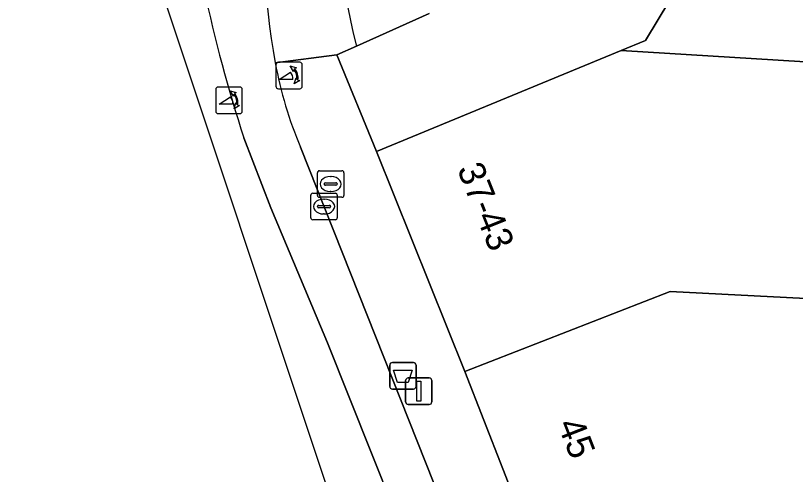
# Model space of a CAD drawing. Extents: x 160856 to 161310, y 384024 to 384878.
# Drawn here: x 160864.45 to 160893.85, y 384793.33 to 384810.61 of the extents above; entities that cross this region are included whole.
import ezdxf

# ---------------------------------------------------------------- set-up
doc = ezdxf.new("R2010")
doc.units = 0
for name, color, linetype in [('IMGEO_Afvalbak', 7, 'Continuous'), ('IMGEO_Brandkraan', 7, 'Continuous'), ('IMGEO_Erf', 7, 'Continuous'), ('IMGEO_Kolk', 7, 'Continuous'), ('IMGEO_Lichtmast', 7, 'Continuous'), ('IMGEO_Pand', 7, 'Continuous'), ('IMGEO_Pand_nummerreeks', 7, 'Continuous'), ('IMGEO_Pand_overbouw', 7, 'Continuous'), ('IMGEO_Poller', 7, 'Continuous'), ('IMGEO_Rijbaan_lokaal_gesloten', 7, 'Continuous'), ('IMGEO_Voetpad_open', 7, 'Continuous')]:
    doc.layers.add(name, color=color, linetype=linetype)

msp = doc.modelspace()

# ---------------------------------------------------------------- linework, layer by layer
at = {"layer": 'IMGEO_Afvalbak'}
for p, q in [((160878.555, 384796.644), (160878.555, 384797.444)), ((160878.555, 384797.444), (160878.555, 384796.644)), ((160878.655, 384797.544), (160879.445, 384797.544)), ((160879.445, 384797.544), (160878.655, 384797.544)), ((160879.545, 384797.444), (160879.545, 384796.644)), ((160879.545, 384796.644), (160879.545, 384797.444)), ((160879.445, 384796.544), (160878.655, 384796.544)), ((160878.655, 384796.544), (160879.445, 384796.544))]:
    msp.add_line(p, q, dxfattribs=at)
msp.add_lwpolyline([(160878.698, 384797.258), (160879.402, 384797.258), (160879.253, 384796.788), (160878.847, 384796.788), (160878.698, 384797.258)], dxfattribs=at)
for centre, start, end in [((160878.655, 384797.444), 90, 180), ((160878.655, 384797.444), 90, 180), ((160879.445, 384797.444), 0, 90), ((160879.445, 384797.444), 360, 90), ((160878.655, 384796.644), 180, 270), ((160878.655, 384796.644), 180, 270), ((160879.445, 384796.644), 270, 0), ((160879.445, 384796.644), 270, 0)]:
    msp.add_arc(centre, 0.1, start, end, dxfattribs=at)
at = {"layer": 'IMGEO_Brandkraan'}
for p, q in [((160875.827, 384803.842), (160875.827, 384804.694)), ((160875.902, 384804.768), (160876.754, 384804.768)), ((160876.828, 384804.694), (160876.828, 384803.842)), ((160876.315, 384804.548), (160876.34, 384804.548)), ((160876.086, 384804.262), (160876.086, 384804.274)), ((160876.524, 384804.225), (160876.126, 384804.225)), ((160876.129, 384804.311), (160876.527, 384804.311)), ((160876.57, 384804.274), (160876.57, 384804.262)), ((160876.338, 384803.988), (160876.313, 384803.988)), ((160876.754, 384803.768), (160875.902, 384803.768))]:
    msp.add_line(p, q, dxfattribs=at)
for points in [[(160875.827, 384803.842), (160875.827, 384804.694)], [(160875.902, 384804.768), (160876.754, 384804.768)], [(160876.828, 384804.694), (160876.828, 384803.842)], [(160876.754, 384803.768), (160875.902, 384803.768)]]:
    msp.add_lwpolyline(points, dxfattribs=at)
for centre, radius, start, end in [((160875.904, 384804.692), 0.0765, 91.552, 178.448), ((160875.904, 384804.692), 0.0765, 91.552, 178.448), ((160876.752, 384804.692), 0.0765, 1.552, 88.448), ((160876.752, 384804.692), 0.0765, 1.552, 88.448), ((160876.126, 384804.271), 0.0403, 85.8775, 175.7526), ((160876.123, 384804.261), 0.0366, 178.938, 274.7102), ((160876.527, 384804.268), 0.043, 264.8664, 352.4533), ((160876.531, 384804.273), 0.0386, 1.7309, 96.639), ((160875.904, 384803.844), 0.0765, 181.552, 268.448), ((160875.904, 384803.844), 0.0765, 181.552, 268.448), ((160876.752, 384803.844), 0.0765, 271.552, 358.448), ((160876.752, 384803.844), 0.0765, 271.552, 358.448)]:
    msp.add_arc(centre, radius, start, end, dxfattribs=at)
for centre, major_axis, ratio, start_param, end_param in [((160876.314, 384804.268), (-0.387, 0.002), 0.722429, 4.712389, 7.853982), ((160876.339, 384804.268), (-0.39, 0.002), 0.717154, 1.570796, 4.712389)]:
    msp.add_ellipse(centre, major_axis=major_axis, ratio=ratio, start_param=start_param, end_param=end_param, dxfattribs=at)
at = {"layer": 'IMGEO_Erf'}
msp.add_lwpolyline([(160961.197, 384839.783), (160936.502, 384833.624), (160932.413, 384832.61), (160896.629, 384823.652), (160888.199, 384809.678), (160887.275, 384809.297), (160905.032, 384808.21), (160908.857, 384799.197), (160924.302, 384798.324), (160924.223, 384796.935), (160953.576, 384795.276), (160956.275, 384793.744), (160958.566, 384819.819)], dxfattribs=at)
at = {"layer": 'IMGEO_Kolk'}
for p, q in [((160875.576, 384802.994), (160875.576, 384803.846)), ((160875.651, 384803.92), (160876.503, 384803.92)), ((160876.577, 384803.846), (160876.577, 384802.994)), ((160876.064, 384803.7), (160876.089, 384803.7)), ((160875.835, 384803.414), (160875.835, 384803.426)), ((160876.273, 384803.377), (160875.875, 384803.377)), ((160875.878, 384803.463), (160876.276, 384803.463)), ((160876.319, 384803.426), (160876.319, 384803.414)), ((160876.503, 384802.92), (160875.651, 384802.92)), ((160876.087, 384803.14), (160876.062, 384803.14))]:
    msp.add_line(p, q, dxfattribs=at)
for points in [[(160875.576, 384802.994), (160875.576, 384803.846)], [(160875.651, 384803.92), (160876.503, 384803.92)], [(160876.577, 384803.846), (160876.577, 384802.994)], [(160876.503, 384802.92), (160875.651, 384802.92)]]:
    msp.add_lwpolyline(points, dxfattribs=at)
for centre, radius, start, end in [((160875.653, 384803.844), 0.0765, 91.552, 178.448), ((160875.653, 384803.844), 0.0765, 91.552, 178.448), ((160876.501, 384803.844), 0.0765, 1.552, 88.448), ((160876.501, 384803.844), 0.0765, 1.552, 88.448), ((160875.875, 384803.423), 0.0403, 85.8775, 175.7526), ((160875.872, 384803.413), 0.0366, 178.938, 274.7102), ((160876.276, 384803.42), 0.043, 264.8664, 352.4533), ((160876.28, 384803.425), 0.0386, 1.7309, 96.639), ((160875.653, 384802.996), 0.0765, 181.552, 268.448), ((160875.653, 384802.996), 0.0765, 181.552, 268.448), ((160876.501, 384802.996), 0.0765, 271.552, 358.448), ((160876.501, 384802.996), 0.0765, 271.552, 358.448)]:
    msp.add_arc(centre, radius, start, end, dxfattribs=at)
for centre, major_axis, ratio, start_param, end_param in [((160876.063, 384803.42), (-0.387, 0.002), 0.722429, 4.712389, 7.853982), ((160876.088, 384803.42), (-0.39, 0.002), 0.717154, 1.570796, 4.712389)]:
    msp.add_ellipse(centre, major_axis=major_axis, ratio=ratio, start_param=start_param, end_param=end_param, dxfattribs=at)
at = {"layer": 'IMGEO_Lichtmast'}
for p, q in [((160879.151, 384796.062), (160879.151, 384796.862)), ((160879.151, 384796.862), (160879.151, 384796.062)), ((160879.251, 384796.962), (160880.041, 384796.962)), ((160880.041, 384796.962), (160879.251, 384796.962)), ((160880.141, 384796.862), (160880.141, 384796.062)), ((160880.141, 384796.062), (160880.141, 384796.862)), ((160880.041, 384795.962), (160879.251, 384795.962)), ((160879.251, 384795.962), (160880.041, 384795.962))]:
    msp.add_line(p, q, dxfattribs=at)
msp.add_lwpolyline([(160879.571, 384796.837), (160879.721, 384796.837), (160879.721, 384796.087), (160879.571, 384796.087), (160879.571, 384796.837)], dxfattribs=at)
for centre, start, end in [((160879.251, 384796.862), 90, 180), ((160879.251, 384796.862), 90, 180), ((160880.041, 384796.862), 0, 90), ((160880.041, 384796.862), 360, 90), ((160879.251, 384796.062), 180, 270), ((160879.251, 384796.062), 180, 270), ((160880.041, 384796.062), 270, 0), ((160880.041, 384796.062), 270, 0)]:
    msp.add_arc(centre, 0.1, start, end, dxfattribs=at)
at = {"layer": 'IMGEO_Pand'}
msp.add_lwpolyline([(160880.046, 384810.689), (160877.299, 384809.467), (160876.56, 384809.138), (160878.06, 384805.492), (160887.275, 384809.297), (160888.199, 384809.678), (160896.629, 384823.652), (160932.413, 384832.61)], dxfattribs=at)
for points in [[(160878.06, 384805.492), (160881.386, 384797.201), (160889.13, 384800.22), (160908.857, 384799.197), (160905.032, 384808.21), (160887.275, 384809.297)], [(160881.386, 384797.201), (160884.249, 384789.865), (160891.991, 384792.888), (160892.427, 384791.772), (160896.734, 384792.911), (160897.291, 384791.284), (160899.216, 384790.615), (160955.868, 384786.532), (160956.275, 384793.744), (160953.576, 384795.276), (160924.223, 384796.935), (160924.302, 384798.324), (160908.857, 384799.197), (160889.13, 384800.22)]]:
    msp.add_lwpolyline(points, close=True, dxfattribs=at)
at = {"layer": 'IMGEO_Pand_overbouw'}
msp.add_lwpolyline([(160877.299, 384809.467), (160880.046, 384810.689)], dxfattribs=at)
msp.add_arc((160898.285, 384814.873), 21.671, 113.6196, 194.4449, dxfattribs=at)
at = {"layer": 'IMGEO_Poller'}
for p, q in [((160875.163, 384808.857), (160874.355, 384808.857)), ((160875.163, 384808.857), (160874.355, 384808.857)), ((160874.261, 384808.762), (160874.261, 384807.955)), ((160874.261, 384808.762), (160874.261, 384807.955)), ((160875.257, 384807.955), (160875.257, 384808.762)), ((160875.257, 384807.955), (160875.257, 384808.762)), ((160872.898, 384807.921), (160872.09, 384807.921)), ((160872.898, 384807.921), (160872.09, 384807.921)), ((160871.996, 384807.826), (160871.996, 384807.019)), ((160871.996, 384807.826), (160871.996, 384807.019)), ((160872.992, 384807.019), (160872.992, 384807.826)), ((160872.992, 384807.019), (160872.992, 384807.826)), ((160874.355, 384807.86), (160875.163, 384807.86)), ((160874.355, 384807.86), (160875.163, 384807.86)), ((160872.09, 384806.924), (160872.898, 384806.924)), ((160872.09, 384806.924), (160872.898, 384806.924))]:
    msp.add_line(p, q, dxfattribs=at)
for points in [[(160874.94, 384808.586), (160874.928, 384808.513), (160874.803, 384808.718)], [(160874.803, 384808.718), (160875.034, 384808.652), (160874.963, 384808.62)], [(160874.896, 384808.213), (160874.383, 384808.213), (160874.813, 384808.488)], [(160874.956, 384808.041), (160875.022, 384808.272), (160875.052, 384808.204)], [(160875.088, 384808.177), (160875.16, 384808.166), (160874.956, 384808.041)], [(160872.675, 384807.65), (160872.663, 384807.577), (160872.538, 384807.782)], [(160872.538, 384807.782), (160872.769, 384807.716), (160872.698, 384807.684)], [(160872.631, 384807.277), (160872.118, 384807.277), (160872.548, 384807.552)], [(160872.691, 384807.105), (160872.757, 384807.336), (160872.787, 384807.268)], [(160872.823, 384807.241), (160872.895, 384807.23), (160872.691, 384807.105)]]:
    msp.add_lwpolyline(points, dxfattribs=at)
for centre, radius, start, end in [((160874.355, 384808.762), 0.0946, 90, 180), ((160874.355, 384808.762), 0.0946, 90, 180), ((160875.163, 384808.762), 0.0946, 0, 90), ((160875.163, 384808.762), 0.0946, 0, 90), ((160874.582, 384808.273), 0.476, 351.7527, 41.1691), ((160874.582, 384808.273), 0.516, 349.3569, 42.2912), ((160874.568, 384808.263), 0.332, 351.3247, 42.4854), ((160872.09, 384807.826), 0.0946, 90, 180), ((160872.09, 384807.826), 0.0946, 90, 180), ((160872.898, 384807.826), 0.0946, 0, 90), ((160872.898, 384807.826), 0.0946, 0, 90), ((160874.355, 384807.955), 0.0946, 180, 270), ((160874.355, 384807.955), 0.0946, 180, 270), ((160875.163, 384807.955), 0.0946, 270, 0), ((160875.163, 384807.955), 0.0946, 270, 0), ((160872.317, 384807.337), 0.476, 351.7527, 41.1691), ((160872.317, 384807.337), 0.516, 349.3569, 42.2912), ((160872.303, 384807.327), 0.332, 351.3247, 42.4854), ((160872.09, 384807.019), 0.0946, 180, 270), ((160872.09, 384807.019), 0.0946, 180, 270), ((160872.898, 384807.019), 0.0946, 270, 0), ((160872.898, 384807.019), 0.0946, 270, 0)]:
    msp.add_arc(centre, radius, start, end, dxfattribs=at)
at = {"layer": 'IMGEO_Rijbaan_lokaal_gesloten'}
for points in [[(160869.019, 384828.851), (160864.45, 384828.072), (160886.966, 384760.496)], [(160873.052, 384806.007), (160874.067, 384803.366), (160876.212, 384798.286), (160884.531, 384777.436), (160890.883, 384755.238), (160892.484, 384755.839), (160893.385, 384756.183), (160887.436, 384774.8), (160875.191, 384805.653)], [(160886.966, 384760.496), (160889.824, 384754.841), (160892.527, 384749.494), (160890.883, 384755.238), (160884.531, 384777.436), (160876.212, 384798.286), (160874.067, 384803.366), (160873.052, 384806.007)]]:
    msp.add_lwpolyline(points, dxfattribs=at)
for centre, radius, start, end in [((160929.426, 384824.175), 59.229, 186.68858, 197.86249), ((160929.426, 384824.175), 59.229, 186.68858, 197.86249), ((160903.973, 384814.212), 30.216, 176.2353, 190.2391), ((160889.197, 384811.576), 15.207, 190.3622, 202.9241)]:
    msp.add_arc(centre, radius, start, end, dxfattribs=at)
at = {"layer": 'IMGEO_Voetpad_open'}
for points in [[(160874.238, 384808.841), (160876.56, 384809.138), (160877.299, 384809.467), (160880.046, 384810.689)], [(160900.915, 384747.341), (160900.002, 384749.671), (160899.318, 384749.406), (160898.94, 384749.571), (160898.771, 384750), (160893.997, 384762.116), (160894.161, 384762.507), (160894.854, 384762.781), (160894.682, 384763.213), (160891.057, 384772.417), (160888.107, 384779.977), (160886.698, 384783.587), (160884.249, 384789.865), (160881.386, 384797.201), (160878.06, 384805.492), (160876.56, 384809.138), (160874.238, 384808.841)], [(160875.191, 384805.653), (160887.436, 384774.8), (160893.385, 384756.183), (160921.747, 384682.423), (160925.586, 384683.954), (160923.413, 384689.547), (160919.502, 384699.614), (160919.422, 384699.819), (160913.229, 384715.759), (160913.036, 384716.255), (160913.025, 384717.51), (160912.528, 384718.769), (160914.414, 384719.534), (160909.277, 384732.755), (160905.955, 384741.304), (160904.378, 384745.364), (160903.382, 384744.987), (160902.333, 384745.503), (160901.445, 384745.94), (160901.332, 384746.227), (160900.915, 384747.341)]]:
    msp.add_lwpolyline(points, dxfattribs=at)
for centre, radius, start, end in [((160903.973, 384814.212), 30.216, 176.2353, 190.2391), ((160889.197, 384811.576), 15.207, 190.3622, 202.9241)]:
    msp.add_arc(centre, radius, start, end, dxfattribs=at)

# ---------------------------------------------------------------- texts
at = {"layer": 'IMGEO_Pand_nummerreeks'}
for s, rotation, p in [('37-43', 291.8469, (160881.082, 384804.834)), ('45', 291.3273, (160884.864, 384795.218))]:
    msp.add_text(s, height=1, rotation=rotation, dxfattribs=at).set_placement(p)

doc.saveas('drawing.dxf')
